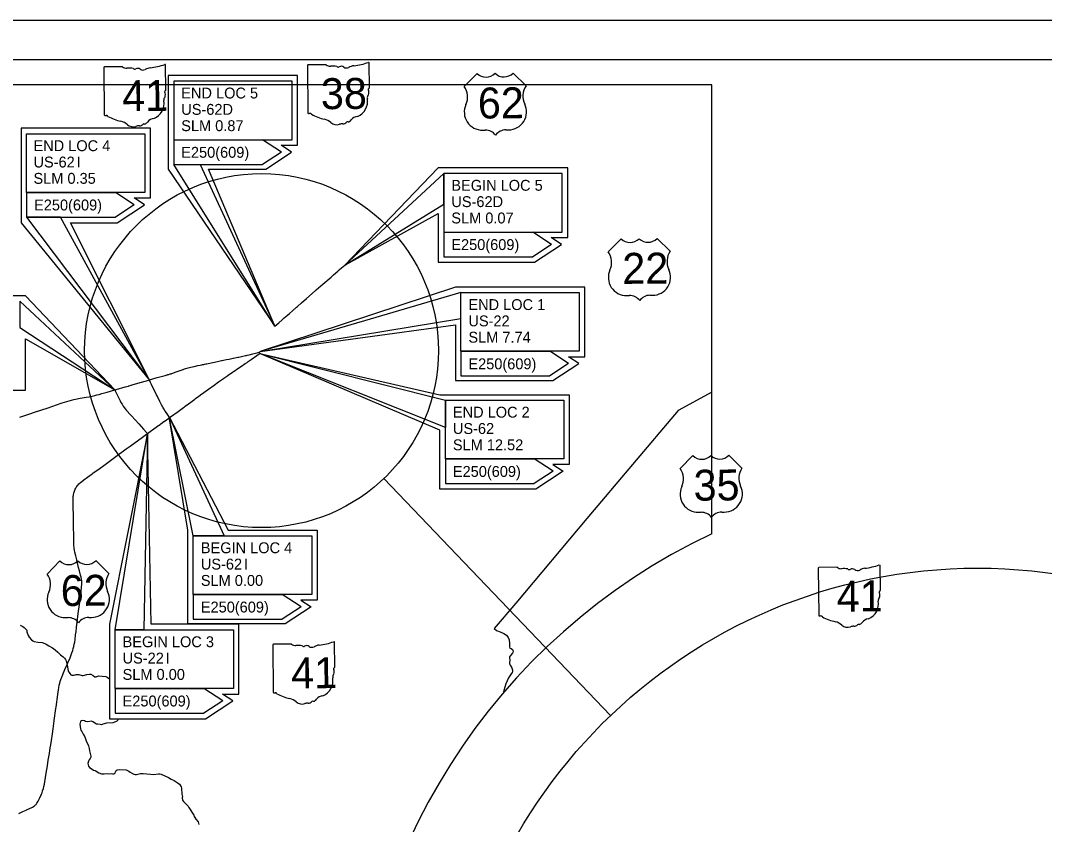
# Model space of a CAD drawing. Extents: x 86259 to 205259, y 423331 to 500331.
# Drawn here: x 126607 to 172720, y 464136 to 500331 of the extents above; entities that cross this region are included whole.
import ezdxf

# ---------------------------------------------------------------- set-up
doc = ezdxf.new("R2010")
doc.units = 0
for name, color, linetype in [('Default', 7, 'Continuous'), ('PM_P_Cells', 7, 'Continuous'), ('PM_X_Cells', 7, 'Continuous'), ('SC_Scratch1', 7, 'Continuous'), ('SH_Border', 7, 'Continuous'), ('SH_Cut_Line', 7, 'Continuous'), ('SH_Data', 7, 'Continuous'), ('SN_P_Signs', 7, 'Continuous'), ('XS_P_Annotation', 7, 'Continuous')]:
    doc.layers.add(name, color=color, linetype=linetype)

msp = doc.modelspace()

# ---------------------------------------------------------------- linework, layer by layer
at = {"layer": 'PM_P_Cells'}
msp.add_line((128491, 483112), (129002, 483264), dxfattribs=at)
for points in [[(139033, 487424), (139077, 487463), (139262, 487624), (139484, 487819), (139879, 488164), (139922, 488202), (140126, 488379), (140224, 488463), (140591, 488781), (140708, 488883), (140897, 489048), (140955, 489099), (141066, 489196), (141141, 489260), (141214, 489323)], [(138055, 486566), (138155, 486651), (138239, 486726), (138389, 486855), (138401, 486866), (138486, 486944), (138557, 487005), (138635, 487072), (138717, 487144), (138856, 487267), (139033, 487424)], [(134898, 484860), (134947, 484870), (134996, 484881), (135063, 484895), (135131, 484910), (135191, 484923), (135270, 484939), (135479, 484983), (135660, 485020), (135672, 485022), (135880, 485065), (136004, 485090), (136184, 485127), (136200, 485130), (136394, 485169), (136435, 485178)], [(136435, 485178), (136612, 485218), (136746, 485248), (136782, 485256), (136820, 485264), (136899, 485282), (137065, 485321), (137196, 485351), (137263, 485370), (137314, 485385), (137355, 485401), (137403, 485424)], [(136721, 484883), (136808, 484942), (136856, 484975), (136998, 485071), (137256, 485248), (137357, 485318), (137375, 485332), (137380, 485336)], [(133793, 484582), (133885, 484612), (133918, 484623), (133931, 484627), (133997, 484646), (134057, 484664), (134151, 484691), (134278, 484723), (134421, 484756), (134596, 484795), (134704, 484818), (134776, 484834)], [(134776, 484834), (134802, 484839)], [(134802, 484839), (134823, 484843), (134834, 484846), (134858, 484851)], [(134858, 484851), (134898, 484860)], [(136151, 484497), (136196, 484528), (136225, 484547), (136400, 484665), (136558, 484773), (136721, 484883)], [(129894, 483430), (129957, 483455), (129995, 483466), (130039, 483477), (130145, 483501), (130273, 483533), (130510, 483600), (130854, 483700), (130877, 483707), (130920, 483719), (131315, 483834), (131464, 483876), (131489, 483883), (131548, 483900), (131678, 483937), (132057, 484048), (132389, 484143), (132410, 484149), (132767, 484253), (133067, 484339), (133119, 484355), (133207, 484383), (133220, 484387), (133240, 484390), (133262, 484393), (133293, 484395)], [(133293, 484395), (133352, 484418), (133393, 484432), (133577, 484504), (133745, 484566), (133793, 484582)], [(135216, 483837), (135322, 483913), (135521, 484059), (135613, 484125), (135748, 484221), (135766, 484233), (135939, 484352), (135952, 484360), (136151, 484497)], [(133327, 482460), (133301, 482496), (133177, 482668), (133122, 482749), (133060, 482846), (133010, 482930), (132955, 483031), (132881, 483177), (132758, 483427), (132734, 483475), (132502, 483950), (132464, 484029), (132429, 484105), (132418, 484130), (132410, 484149)], [(134864, 483580), (134972, 483659), (135180, 483810), (135216, 483837)], [(129002, 483264), (129086, 483283), (129295, 483324), (129571, 483370), (129701, 483393), (129894, 483430)], [(130854, 483700), (130864, 483676), (130874, 483655), (130960, 483472), (131032, 483325), (131092, 483208), (131132, 483137), (131182, 483053), (131236, 482971), (131283, 482904), (131334, 482839), (131386, 482777), (131561, 482579), (131602, 482533), (131933, 482167), (132142, 481936), (132296, 481765), (132322, 481735)], [(133941, 482905), (133989, 482940), (134021, 482963), (134179, 483079), (134284, 483156), (134458, 483286)], [(134458, 483286), (134506, 483322), (134582, 483377), (134695, 483459), (134715, 483474)], [(134715, 483474), (134864, 483580)], [(126571, 482480), (126759, 482540), (126976, 482612), (127287, 482716), (127801, 482886), (128066, 482973), (128222, 483024), (128491, 483112)], [(133070, 482276), (133327, 482460), (133360, 482484), (133704, 482733), (133941, 482905)], [(132280, 481704), (132322, 481735), (132393, 481786), (132676, 481993)], [(132676, 481993), (132697, 482008), (132796, 482079)], [(132796, 482079), (132824, 482099), (132893, 482149), (132927, 482174), (133068, 482275), (133070, 482276)], [(129854, 479939), (129883, 479963), (130129, 480138), (130420, 480350), (130963, 480745), (131373, 481044), (131545, 481170), (131770, 481333), (132034, 481526), (132280, 481704)], [(128985, 478313), (128984, 478327), (128982, 478540), (128978, 478770), (128979, 478851), (128982, 478900), (128988, 478949), (128996, 478997), (129007, 479045), (129020, 479092), (129035, 479139), (129052, 479184), (129073, 479229), (129095, 479272), (129120, 479315), (129147, 479355), (129176, 479395), (129207, 479432), (129241, 479468), (129275, 479503), (129312, 479536), (129362, 479577), (129454, 479647), (129626, 479772), (129829, 479920)], [(129829, 479920), (129841, 479928), (129854, 479939)], [(129091, 472677), (129107, 472805), (129132, 473017), (129160, 473245), (129210, 473636), (129261, 474043), (129292, 474271), (129332, 474593), (129359, 474841), (129367, 474939), (129370, 475005), (129368, 475054), (129368, 475057), (129363, 475120), (129354, 475185), (129338, 475266), (129316, 475362), (129267, 475553), (129226, 475712), (129140, 476045), (129092, 476236), (129055, 476396), (129035, 476492), (129025, 476556), (129019, 476621), (129016, 476687), (129012, 476818), (129010, 476982), (129007, 477146), (129005, 477244), (129000, 477441), (128995, 477671), (128992, 477851), (128991, 477999), (128988, 478146), (128985, 478313)], [(128199, 469358), (128207, 469418), (128283, 469987), (128315, 470198), (128332, 470295), (128356, 470407), (128379, 470503), (128401, 470581), (128426, 470659), (128466, 470767), (128514, 470889), (128610, 471115), (128705, 471335), (128740, 471416), (128837, 471643), (128892, 471780), (128926, 471872), (128957, 471966), (128984, 472061), (129009, 472156), (129029, 472253), (129047, 472350), (129063, 472464), (129091, 472677)], [(127704, 466056), (127705, 466060), (127767, 466448), (127819, 466772), (127860, 467032), (127909, 467339), (127947, 467583), (127970, 467728), (128000, 467923), (128041, 468216), (128074, 468443), (128124, 468800), (128127, 468825), (128199, 469358)], [(126532, 464629), (126716, 464715), (126720, 464717), (126868, 464785), (126884, 464791), (126988, 464840), (127046, 464868), (127091, 464892), (127149, 464924), (127191, 464950), (127232, 464977), (127258, 464997), (127283, 465019), (127306, 465043), (127328, 465068), (127347, 465095), (127374, 465137), (127397, 465180), (127465, 465312), (127529, 465445), (127546, 465482), (127556, 465505), (127579, 465566), (127605, 465645), (127638, 465755), (127662, 465850), (127684, 465947), (127704, 466056)]]:
    msp.add_lwpolyline(points, dxfattribs=at)
at = {"layer": 'PM_X_Cells'}
for points in [[(157733, 483604), (156216, 482780), (152114, 477913), (148909, 474096), (147936, 472955), (148047, 472875), (148207, 472813), (148377, 472734), (148489, 472659), (148569, 472551), (148611, 472445), (148628, 472288), (148622, 472180), (148628, 472128), (148648, 472078), (148704, 472062), (148756, 472013), (148782, 471963), (148787, 471911), (148765, 471853), (148671, 471747), (148634, 471683), (148630, 471633), (148638, 471527), (148626, 471423), (148629, 471363), (148653, 471307), (148727, 471196), (148755, 471090), (148755, 471038), (148741, 470980), (148706, 470920), (148583, 470746), (148515, 470600), (148464, 470470), (148367, 470176), (148337, 470050)], [(126598, 473109), (126712, 473055), (126780, 473006), (126840, 472944), (126886, 472878), (126900, 472808), (126957, 472639), (126995, 472575), (127105, 472452), (127163, 472404), (127217, 472372), (127391, 472343), (127586, 472323), (127708, 472290), (127766, 472262), (127880, 472180), (128044, 472095), (128174, 471996), (128296, 471890), (128412, 471771), (128523, 471687), (128583, 471626), (128631, 471570), (128665, 471508), (128728, 471229), (128760, 471041), (128796, 470983), (128822, 470930), (128868, 470880), (128924, 470858), (129014, 470852), (129064, 470876), (129116, 470887), (129240, 470889), (129379, 470847), (129431, 470838), (129593, 470886), (129715, 470904), (129777, 470901), (129887, 470837), (129955, 470779), (130014, 470780), (130118, 470822), (130448, 470793), (130512, 470769), (130616, 470687)], [(131022, 468899), (131020, 468892), (130987, 468840), (130941, 468788), (130887, 468754), (130767, 468707), (130482, 468694), (130310, 468652), (130255, 468628), (130197, 468644), (130075, 468647), (130023, 468655), (129863, 468762), (129801, 468786), (129647, 468758), (129538, 468773), (129486, 468797), (129416, 468815), (129358, 468803), (129306, 468767), (129288, 468711), (129282, 468655), (129305, 468441), (129331, 468379), (129367, 468324), (129426, 468202), (129500, 468084), (129562, 467907), (129677, 467674), (129705, 467554), (129715, 467448), (129782, 467211), (129780, 467161), (129752, 467109), (129699, 467047), (129663, 466989), (129633, 466877), (129675, 466757), (129718, 466705), (129838, 466620), (129896, 466588), (129964, 466566), (130139, 466465), (130255, 466424), (130313, 466418), (130375, 466414), (130489, 466426), (130591, 466419), (130695, 466425), (130754, 466415), (130810, 466417), (130864, 466453), (130880, 466513), (130914, 466565), (130964, 466594), (131079, 466612), (131371, 466595), (131489, 466541), (131549, 466494), (131657, 466436), (131713, 466396), (131769, 466380), (131835, 466381), (132018, 466427), (132128, 466433), (132457, 466409), (132597, 466381), (132818, 466420), (132876, 466422), (132938, 466406), (133270, 466251), (133390, 466180), (133524, 466116), (133658, 466031), (133774, 465947), (133838, 465826), (133858, 465772), (133871, 465509), (133896, 465387), (133886, 465335), (133904, 465227), (133944, 465167), (133998, 465128), (134156, 464964), (134194, 464909), (134417, 464554), (134425, 464502), (134465, 464450), (134499, 464382), (134602, 464251), (134628, 464197), (134638, 464131)]]:
    msp.add_lwpolyline(points, dxfattribs=at)
at = {"layer": 'SC_Scratch1'}
for p, q in [((133258, 494713), (133258, 493642)), ((137648, 493642), (138814, 494407)), ((138814, 494407), (138347, 494713)), ((133258, 493642), (138055, 486565)), ((138055, 486565), (135074, 493642)), ((135074, 493642), (137648, 493642)), ((145420, 493699), (141213, 489322)), ((126630, 492342), (126630, 491229)), ((130958, 491229), (132186, 492035)), ((132186, 492035), (131720, 492342)), ((141213, 489322), (145420, 491645)), ((145420, 491645), (145420, 490559)), ((126630, 491229), (132420, 484134)), ((132420, 484134), (128855, 491229)), ((128855, 491229), (130958, 491229)), ((145420, 490559), (145420, 489446)), ((149748, 489446), (150976, 490253)), ((150976, 490253), (150510, 490559)), ((145420, 489446), (149748, 489446)), ((130854, 483700), (126833, 487943)), ((146189, 488329), (137403, 485424)), ((137403, 485424), (146189, 486628)), ((146189, 486628), (146189, 485189)), ((126833, 484803), (126833, 485995)), ((126833, 485995), (130854, 483700)), ((137380, 485336), (145490, 483486)), ((145490, 481894), (137380, 485336)), ((146189, 485189), (146189, 484118)), ((151745, 484883), (151279, 485189)), ((126833, 483691), (126833, 484803)), ((150580, 484118), (151745, 484883)), ((146189, 484118), (150580, 484118)), ((122505, 483691), (126833, 483691)), ((145490, 483486), (151320, 483486)), ((151320, 483486), (151320, 480346)), ((133301, 482496), (135952, 477381)), ((134140, 477381), (133301, 482496)), ((145490, 479234), (145490, 481894)), ((132322, 481735), (130616, 473151)), ((132485, 473151), (132322, 481735)), ((151046, 480040), (149818, 479234)), ((151320, 480346), (150580, 480346)), ((150580, 480346), (151046, 480040)), ((149818, 479234), (145490, 479234)), ((134140, 474241), (134140, 477381)), ((135952, 477381), (139970, 477381)), ((139970, 477381), (139970, 474241)), ((134140, 473170), (134140, 474241)), ((139970, 474241), (139230, 474241)), ((139230, 474241), (139696, 473935)), ((139696, 473935), (138531, 473170)), ((130616, 473151), (130616, 470011)), ((136446, 473151), (132485, 473151)), ((138531, 473170), (134140, 473170)), ((136446, 470011), (136446, 473151)), ((130616, 470011), (130616, 468899)), ((136172, 469705), (135706, 470011)), ((135706, 470011), (136446, 470011)), ((134945, 468899), (136172, 469705)), ((130616, 468899), (134945, 468899))]:
    msp.add_line(p, q, dxfattribs=at)
for points in [[(138347, 494713), (139088, 494713), (139088, 497853), (133258, 497853), (133258, 494713)], [(157733, 477217), (157733, 497437), (93135, 497437), (93135, 426333), (157733, 426333)], [(157733, 477217), (157733, 497437), (93135, 497437), (93135, 426333), (157733, 426333)], [(131720, 492342), (132460, 492342), (132460, 495482), (126630, 495482), (126630, 492342)], [(150510, 490559), (151250, 490559), (151250, 493699), (145420, 493699)], [(126833, 487943), (121003, 487943), (121003, 484803), (121743, 484803)], [(151279, 485189), (152019, 485189), (152019, 488329), (146189, 488329)]]:
    msp.add_lwpolyline(points, dxfattribs=at)
msp.add_arc((169707, 451775), 28119, 115.2046, 244.7954, dxfattribs=at)
msp.add_arc((169707, 451775), 28119, 115.2046, 244.7954, dxfattribs=at)
at = {"layer": 'SH_Border'}
msp.add_line((142972, 479715), (153181, 469045), dxfattribs=at)
msp.add_lwpolyline([(91509, 498581), (203509, 498581), (203509, 425081), (91509, 425081)], close=True, dxfattribs=at)
for centre, radius in [((137463, 485471), 7968), ((169707, 451775), 23903)]:
    msp.add_circle(centre, radius, dxfattribs=at)
at = {"layer": 'SH_Cut_Line'}
msp.add_lwpolyline([(86259, 423331), (205259, 423331), (205259, 500331), (86259, 500331)], close=True, dxfattribs=at)
at = {"layer": 'SH_Data'}
for p, q in [((133508, 494963), (133508, 493851)), ((133508, 494963), (137511, 494963)), ((138358, 494407), (137511, 494963)), ((138358, 494407), (137511, 493851)), ((133508, 493851), (137511, 493851)), ((126880, 492592), (126880, 491479)), ((126880, 492592), (130884, 492592)), ((131731, 492035), (130884, 492592)), ((131731, 492035), (130884, 491479)), ((126880, 491479), (130884, 491479)), ((145670, 490809), (145670, 489696)), ((145670, 490809), (149674, 490809)), ((150521, 490253), (149674, 490809)), ((150521, 490253), (149674, 489696)), ((145670, 489696), (149674, 489696)), ((146439, 485439), (146439, 484327)), ((146439, 485439), (150443, 485439)), ((151290, 484883), (150443, 485439)), ((151290, 484883), (150443, 484327)), ((146439, 484327), (150443, 484327)), ((145740, 480596), (145740, 479484)), ((145740, 480596), (149744, 480596)), ((150591, 480040), (149744, 480596)), ((150591, 480040), (149744, 479484)), ((145740, 479484), (149744, 479484)), ((134390, 474491), (134390, 473379)), ((134390, 474491), (138393, 474491)), ((139240, 473935), (138393, 474491)), ((139240, 473935), (138393, 473379)), ((134390, 473379), (138393, 473379)), ((130866, 470261), (130866, 469149)), ((130866, 470261), (134870, 470261)), ((135717, 469705), (134870, 470261)), ((135717, 469705), (134870, 469149)), ((130866, 469149), (134870, 469149))]:
    msp.add_line(p, q, dxfattribs=at)
for points in [[(133508, 494963), (138838, 494963), (138838, 497603), (133508, 497603)], [(132210, 492592), (126880, 492592), (126880, 495232), (132210, 495232)], [(134691, 493851), (138055, 486565), (133508, 493851)], [(145670, 493449), (141213, 489322), (145670, 492061)], [(145670, 490809), (151000, 490809), (151000, 493449), (145670, 493449)], [(126880, 491479), (132420, 484134), (128412, 491479)], [(146439, 488079), (137403, 485424), (146439, 486915)], [(146439, 488079), (151769, 488079), (151769, 485439), (146439, 485439)], [(126583, 486509), (130854, 483700), (126583, 487693)], [(145740, 482010), (137380, 485336), (145740, 483236)], [(145740, 483236), (151070, 483236), (151070, 480596), (145740, 480596)], [(134390, 477131), (133301, 482496), (135778, 477131)], [(130866, 472901), (132322, 481735), (132159, 472901)], [(134390, 477131), (139720, 477131), (139720, 474491), (134390, 474491)], [(130866, 472901), (136196, 472901), (136196, 470261), (130866, 470261)]]:
    msp.add_lwpolyline(points, close=True, dxfattribs=at)
at = {"layer": 'SN_P_Signs'}
for p, q in [((147165, 497946), (146590, 497361)), ((149374, 497387), (148789, 497961)), ((147421, 495396), (147537, 495397)), ((148465, 495406), (148581, 495407)), ((153652, 490501), (153077, 489916)), ((155861, 489942), (155276, 490517)), ((153908, 487951), (154024, 487952)), ((154952, 487961), (155068, 487962)), ((156885, 480741), (156310, 480156)), ((159094, 480182), (158509, 480756)), ((157141, 478191), (157257, 478192)), ((158185, 478201), (158301, 478202)), ((128382, 475999), (127807, 475413)), ((130592, 475439), (130006, 476014)), ((128638, 473449), (128754, 473450)), ((129682, 473458), (129798, 473459))]:
    msp.add_line(p, q, dxfattribs=at)
for centre, radius, start, end in [((147567, 498364), 580, 226.1115, 314.9656), ((148379, 498372), 580, 226.1115, 314.9656), ((145929, 496889), 812, 335.0857, 35.5395), ((150044, 496927), 812, 145.5376, 205.9914), ((147404, 496208), 812, 155.3705, 271.1768), ((148582, 496219), 812, 269.9003, 25.7066), ((147542, 494817), 580, 37.4084, 90.5385), ((148470, 494826), 580, 90.5385, 143.6686), ((154054, 490919), 580, 226.1115, 314.9656), ((154866, 490927), 580, 226.1115, 314.9656), ((152416, 489444), 812, 335.0857, 35.5395), ((156531, 489482), 812, 145.5376, 205.9914), ((153891, 488763), 812, 155.3705, 271.1768), ((155069, 488774), 812, 269.9003, 25.7066), ((154029, 487372), 580, 37.4084, 90.5385), ((154957, 487381), 580, 90.5385, 143.6686), ((157287, 481159), 580, 226.1115, 314.9656), ((158099, 481167), 580, 226.1115, 314.9656), ((155649, 479684), 812, 335.0857, 35.5395), ((159764, 479722), 812, 145.5376, 205.9914), ((157124, 479003), 812, 155.3705, 271.1768), ((158302, 479014), 812, 269.9003, 25.7066), ((157262, 477612), 580, 37.4084, 90.5385), ((158190, 477621), 580, 90.5385, 143.6686), ((128784, 476417), 580, 226.1115, 314.9656), ((129596, 476424), 580, 226.1115, 314.9656), ((131261, 474980), 812, 145.5376, 205.9914), ((127147, 474941), 812, 335.0857, 35.5395), ((128621, 474260), 812, 155.3705, 271.1768), ((129800, 474272), 812, 269.9003, 25.7066), ((128760, 472870), 580, 37.4084, 90.5385), ((129688, 472878), 580, 90.5385, 143.6686)]:
    msp.add_arc(centre, radius, start, end, dxfattribs=at)
at = {"layer": 'XS_P_Annotation'}
for p, q in [((130359, 498203), (130379, 496090)), ((131202, 498247), (130386, 498239)), ((133153, 497212), (133143, 498318)), ((139525, 498296), (139545, 496183)), ((140367, 498340), (139552, 498332)), ((142318, 497305), (142308, 498411)), ((133153, 497213), (133153, 497212)), ((142318, 497306), (142318, 497305)), ((162533, 475673), (162553, 473560)), ((163376, 475717), (162560, 475710)), ((165327, 474682), (165317, 475788)), ((165327, 474683), (165327, 474682)), ((137966, 472215), (137986, 470102)), ((138808, 472259), (137993, 472252)), ((140759, 471225), (140749, 472330)), ((140759, 471225), (140759, 471225))]:
    msp.add_line(p, q, dxfattribs=at)
for centre, radius, start, end in [((130391, 498208), 32.3, 98.6686, 188.6686), ((131394, 498494), 313, 232.1581, 271.6504), ((131511, 497064), 1123, 81.0252, 95.5268), ((131755, 498231), 90.3, 220.3306, 297.6409), ((131890, 497988), 188, 55.0052, 119.6797), ((132129, 498326), 226, 234.3948, 295.3667), ((132534, 497614), 594, 97.8847, 121.3074), ((132124, 501137), 2953, 276.383, 289.445), ((133112, 498322), 31, 352.4006, 98.2765), ((139557, 498301), 32.3, 98.6686, 188.6686), ((140559, 498587), 313, 232.1581, 271.6504), ((140676, 497157), 1123, 81.0252, 95.5268), ((140920, 498324), 90.3, 220.3306, 297.6409), ((141055, 498081), 188, 55.0052, 119.6797), ((141294, 498419), 226, 234.3948, 295.3667), ((141699, 497707), 594, 97.8847, 121.3074), ((141290, 501230), 2953, 276.383, 289.445), ((142277, 498415), 31, 352.4006, 98.2765), ((133147, 497131), 48, 108.4825, 210.8755), ((132843, 496989), 288, 340.5715, 24.1881), ((133120, 497208), 33.2, 290.1424, 8.2727), ((142312, 497224), 48, 108.4825, 210.8755), ((142008, 497081), 288, 340.5715, 24.1881), ((142285, 497301), 33.2, 290.1424, 8.2727), ((132332, 496601), 739, 292.8474, 9.5244), ((133268, 496751), 210, 137.345, 187.4681), ((141498, 496694), 739, 292.8474, 9.5244), ((142434, 496844), 210, 137.345, 187.4681), ((139577, 496178), 32.5, 172.4969, 258.8452), ((130411, 496085), 32.5, 172.4969, 258.8452), ((130414, 496302), 248, 267.8775, 281.1424), ((130468, 495969), 89.5, 30.2869, 93.8103), ((131581, 497878), 2132, 240.9515, 257.737), ((130971, 495146), 667, 47.7227, 76.3745), ((132138, 495901), 239, 283.4117, 323.8157), ((132654, 495518), 404, 94.9417, 143.1153), ((139580, 496395), 248, 267.8775, 281.1424), ((139634, 496062), 89.5, 30.2869, 93.8103), ((140746, 497971), 2132, 240.9515, 257.737), ((140136, 495239), 667, 47.7227, 76.3745), ((140850, 496062), 423, 231.2389, 286.8304), ((141127, 495907), 226, 269.3156, 316.0878), ((141333, 495704), 63.5, 66.2903, 133.187), ((141303, 495994), 239, 283.4117, 323.8157), ((141819, 495611), 404, 94.9417, 143.1153), ((131685, 495970), 423, 231.2389, 286.8304), ((131936, 495241), 348, 86.2337, 111.7485), ((131962, 495814), 226, 269.3156, 316.0878), ((132168, 495611), 63.5, 66.2903, 133.187), ((141102, 495334), 348, 86.2337, 111.7485), ((162565, 475678), 32.3, 98.6686, 188.6686), ((163568, 475964), 313, 232.1581, 271.6504), ((163685, 474534), 1123, 81.0252, 95.5268), ((163929, 475701), 90.3, 220.3306, 297.6409), ((164064, 475458), 188, 55.0052, 119.6797), ((164303, 475796), 226, 234.3948, 295.3667), ((164708, 475084), 594, 97.8847, 121.3074), ((164298, 478607), 2953, 276.383, 289.445), ((165286, 475792), 31, 352.4006, 98.2765), ((165321, 474601), 48, 108.4825, 210.8755), ((165017, 474459), 288, 340.5715, 24.1881), ((165294, 474678), 33.2, 290.1424, 8.2727), ((164506, 474071), 739, 292.8474, 9.5244), ((165442, 474221), 210, 137.345, 187.4681), ((162585, 473555), 32.5, 172.4969, 258.8452), ((162588, 473772), 248, 267.8775, 281.1424), ((162642, 473439), 89.5, 30.2869, 93.8103), ((163755, 475348), 2132, 240.9515, 257.737), ((163145, 472616), 667, 47.7227, 76.3745), ((164136, 473284), 226, 269.3156, 316.0878), ((164342, 473081), 63.5, 66.2903, 133.187), ((164312, 473371), 239, 283.4117, 323.8157), ((164828, 472988), 404, 94.9417, 143.1153), ((163859, 473440), 423, 231.2389, 286.8304), ((164110, 472711), 348, 86.2337, 111.7485), ((137998, 472220), 32.3, 98.6686, 188.6686), ((139000, 472507), 313, 232.1581, 271.6504), ((139117, 471076), 1123, 81.0252, 95.5268), ((140140, 471626), 594, 97.8847, 121.3074), ((139731, 475149), 2953, 276.383, 289.445), ((140718, 472334), 31, 352.4006, 98.2765), ((139361, 472244), 90.3, 220.3306, 297.6409), ((139496, 472001), 188, 55.0052, 119.6797), ((139735, 472338), 226, 234.3948, 295.3667), ((140875, 470763), 210, 137.345, 187.4681), ((140753, 471143), 48, 108.4825, 210.8755), ((140449, 471001), 288, 340.5715, 24.1881), ((140726, 471220), 33.2, 290.1424, 8.2727), ((139939, 470614), 739, 292.8474, 9.5244), ((138018, 470098), 32.5, 172.4969, 258.8452), ((138021, 470314), 248, 267.8775, 281.1424), ((138075, 469981), 89.5, 30.2869, 93.8103), ((139187, 471890), 2132, 240.9515, 257.737), ((140260, 469530), 404, 94.9417, 143.1153), ((138577, 469158), 667, 47.7227, 76.3745), ((139291, 469982), 423, 231.2389, 286.8304), ((139543, 469253), 348, 86.2337, 111.7485), ((139568, 469826), 226, 269.3156, 316.0878), ((139774, 469623), 63.5, 66.2903, 133.187), ((139744, 469914), 239, 283.4117, 323.8157)]:
    msp.add_arc(centre, radius, start, end, dxfattribs=at)

# ---------------------------------------------------------------- texts
at = {"layer": 'Default'}
for s, p in [('END LOC 5', (133846, 496820)), ('US-62D', (133846, 496085)), ('SLM 0.87', (133846, 495350)), ('END LOC 4', (127192, 494449)), ('E250(609)', (133846, 494152)), ('US-62', (127192, 493714)), ('I', (129132, 493714)), ('SLM 0.35', (127192, 492979)), ('BEGIN LOC 5', (146008, 492666)), ('E250(609)', (127219, 491781)), ('US-62D', (146008, 491931)), ('SLM 0.07', (146008, 491196)), ('E250(609)', (146008, 489998)), ('END LOC 1', (146777, 487297)), ('US-22', (146777, 486562)), ('SLM 7.74', (146777, 485827)), ('E250(609)', (146777, 484629)), ('END LOC 2', (146078, 482453)), ('US-62', (146078, 481718)), ('SLM 12.52', (146078, 480983)), ('E250(609)', (146078, 479785)), ('BEGIN LOC 4', (134728, 476349)), ('US-62', (134728, 475614)), ('I', (136668, 475614)), ('SLM 0.00', (134728, 474879)), ('E250(609)', (134728, 473680)), ('BEGIN LOC 3', (131205, 472118)), ('US-22', (131205, 471383)), ('I', (133145, 471383)), ('SLM 0.00', (131205, 470648)), ('E250(609)', (131205, 469450))]:
    msp.add_text(s, height=490, dxfattribs=at).set_placement(p)
at = {"layer": 'SN_P_Signs'}
for s, p in [('62', (147208, 495916)), ('22', (153712, 488472)), ('35', (156923, 478711)), ('62', (128425, 473969))]:
    msp.add_text(s, height=1392.2, rotation=0.5385, dxfattribs=at).set_placement(p)
at = {"layer": 'XS_P_Annotation'}
for s, p in [('41', (131192, 496246)), ('38', (140139, 496337)), ('41', (163366, 473716)), ('41', (138799, 470259))]:
    msp.add_text(s, height=1392.2, rotation=0.5385, dxfattribs=at).set_placement(p)

doc.saveas('drawing.dxf')
